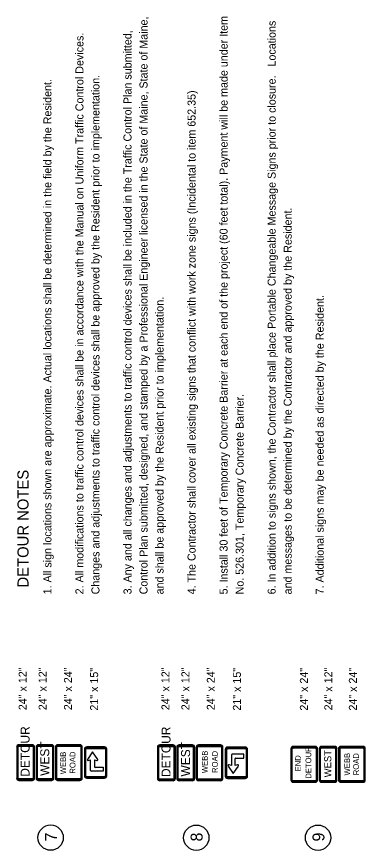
# Model space of a CAD drawing. Extents: x 1123038 to 1172987, y 554419 to 623636.
# Drawn here: x 1135053 to 1139929, y 554424 to 566087 of the extents above; entities that cross this region are included whole.
import ezdxf

# ---------------------------------------------------------------- set-up
doc = ezdxf.new("R2010")
doc.units = 0
for name, color, linetype in [('ANNOTATION', 7, 'Continuous'), ('D_Text_Standard', 7, 'Continuous'), ('Default', 7, 'Continuous')]:
    doc.layers.add(name, color=color, linetype=linetype)

msp = doc.modelspace()

# ---------------------------------------------------------------- linework, layer by layer
at = {"layer": 'D_Text_Standard'}
for centre in [(1135528, 554602), (1137565, 554601), (1139268, 554601)]:
    msp.add_circle(centre, 177, dxfattribs=at)
at = {"layer": 'Default'}
for p, q in [((1135053, 555871), (1135053, 555433)), ((1135061, 555871), (1135061, 555433)), ((1135074, 555433), (1135074, 555871)), ((1135272, 555902), (1135084, 555902)), ((1135272, 555894), (1135084, 555894)), ((1135084, 555881), (1135272, 555881)), ((1135282, 555871), (1135282, 555433)), ((1135295, 555433), (1135295, 555871)), ((1135303, 555433), (1135303, 555871)), ((1135324, 555871), (1135324, 555433)), ((1135332, 555871), (1135332, 555433)), ((1135345, 555433), (1135345, 555871)), ((1135543, 555902), (1135355, 555902)), ((1135543, 555894), (1135355, 555894)), ((1135355, 555881), (1135543, 555881)), ((1135553, 555871), (1135553, 555433)), ((1135566, 555433), (1135566, 555871)), ((1135574, 555433), (1135574, 555871)), ((1135595, 555871), (1135595, 555433)), ((1135603, 555871), (1135603, 555433)), ((1135616, 555433), (1135616, 555871)), ((1135938, 555902), (1135626, 555902)), ((1135938, 555894), (1135626, 555894)), ((1135626, 555881), (1135938, 555881)), ((1135949, 555871), (1135949, 555433)), ((1135962, 555433), (1135962, 555871)), ((1135970, 555433), (1135970, 555871)), ((1136282, 555871), (1136032, 555871)), ((1136282, 555863), (1136032, 555863)), ((1136032, 555850), (1136282, 555850)), ((1137022, 555868), (1137022, 555430)), ((1137030, 555868), (1137030, 555430)), ((1137043, 555430), (1137043, 555868)), ((1137241, 555899), (1137053, 555899)), ((1137241, 555891), (1137053, 555891)), ((1137053, 555878), (1137241, 555878)), ((1137251, 555868), (1137251, 555430)), ((1137264, 555430), (1137264, 555868)), ((1137272, 555430), (1137272, 555868)), ((1137293, 555868), (1137293, 555430)), ((1137300, 555868), (1137300, 555430)), ((1137313, 555430), (1137313, 555868)), ((1137511, 555899), (1137324, 555899)), ((1137511, 555891), (1137324, 555891)), ((1137324, 555878), (1137511, 555878)), ((1137522, 555868), (1137522, 555430)), ((1137535, 555430), (1137535, 555868)), ((1137543, 555430), (1137543, 555868)), ((1137563, 555868), (1137563, 555430)), ((1137571, 555868), (1137571, 555430)), ((1137584, 555430), (1137584, 555868)), ((1137907, 555899), (1137595, 555899)), ((1137907, 555891), (1137595, 555891)), ((1137595, 555878), (1137907, 555878)), ((1137918, 555868), (1137918, 555430)), ((1137931, 555430), (1137931, 555868)), ((1137938, 555430), (1137938, 555868)), ((1138251, 555868), (1138001, 555868)), ((1138251, 555860), (1138001, 555860)), ((1139231, 555877), (1138919, 555877)), ((1139231, 555869), (1138919, 555869)), ((1138919, 555856), (1139231, 555856)), ((1139502, 555877), (1139315, 555877)), ((1139502, 555869), (1139315, 555869)), ((1139315, 555856), (1139502, 555856)), ((1139898, 555877), (1139585, 555877)), ((1139898, 555869), (1139585, 555869)), ((1139585, 555856), (1139898, 555856)), ((1136001, 555840), (1136001, 555465)), ((1136009, 555840), (1136009, 555465)), ((1136022, 555465), (1136022, 555840)), ((1136114, 555801), (1136043, 555697)), ((1136186, 555697), (1136114, 555801)), ((1136293, 555840), (1136293, 555465)), ((1136306, 555465), (1136306, 555840)), ((1136313, 555465), (1136313, 555840)), ((1137970, 555837), (1137970, 555462)), ((1137977, 555837), (1137977, 555462)), ((1137991, 555462), (1137991, 555837)), ((1138001, 555847), (1138251, 555847)), ((1138056, 555758), (1138056, 555613)), ((1138231, 555770), (1138067, 555770)), ((1138231, 555715), (1138231, 555770)), ((1138261, 555837), (1138261, 555462)), ((1138274, 555462), (1138274, 555837)), ((1138282, 555462), (1138282, 555837)), ((1138887, 555846), (1138887, 555408)), ((1138895, 555846), (1138895, 555408)), ((1138908, 555408), (1138908, 555846)), ((1139242, 555846), (1139242, 555408)), ((1139255, 555408), (1139255, 555846)), ((1139262, 555408), (1139262, 555846)), ((1139283, 555846), (1139283, 555408)), ((1139291, 555846), (1139291, 555408)), ((1139304, 555408), (1139304, 555846)), ((1139512, 555846), (1139512, 555408)), ((1139526, 555408), (1139526, 555846)), ((1139533, 555408), (1139533, 555846)), ((1139554, 555846), (1139554, 555408)), ((1139562, 555846), (1139562, 555408)), ((1139575, 555408), (1139575, 555846)), ((1139908, 555846), (1139908, 555408)), ((1139921, 555408), (1139921, 555846)), ((1139929, 555408), (1139929, 555846)), ((1136054, 555681), (1136087, 555689)), ((1136087, 555543), (1136087, 555689)), ((1136142, 555689), (1136174, 555681)), ((1136142, 555689), (1136142, 555593)), ((1138056, 555613), (1138023, 555620)), ((1138110, 555613), (1138110, 555708)), ((1138143, 555620), (1138110, 555613)), ((1138118, 555715), (1138231, 555715)), ((1136263, 555531), (1136099, 555531)), ((1136149, 555586), (1136263, 555586)), ((1136263, 555586), (1136263, 555531)), ((1138012, 555604), (1138083, 555501)), ((1138083, 555501), (1138154, 555604)), ((1135272, 555423), (1135084, 555423)), ((1135084, 555410), (1135272, 555410)), ((1135084, 555402), (1135272, 555402)), ((1135543, 555423), (1135355, 555423)), ((1135355, 555410), (1135543, 555410)), ((1135355, 555402), (1135543, 555402)), ((1135938, 555423), (1135626, 555423)), ((1135626, 555410), (1135938, 555410)), ((1135626, 555402), (1135938, 555402)), ((1136282, 555454), (1136032, 555454)), ((1136032, 555441), (1136282, 555441)), ((1136032, 555433), (1136282, 555433)), ((1137241, 555420), (1137053, 555420)), ((1137053, 555407), (1137241, 555407)), ((1137053, 555399), (1137241, 555399)), ((1137511, 555420), (1137324, 555420)), ((1137324, 555407), (1137511, 555407)), ((1137324, 555399), (1137511, 555399)), ((1137907, 555420), (1137595, 555420)), ((1137595, 555407), (1137907, 555407)), ((1137595, 555399), (1137907, 555399)), ((1138251, 555451), (1138001, 555451)), ((1138001, 555438), (1138251, 555438)), ((1138001, 555430), (1138251, 555430)), ((1139231, 555398), (1138919, 555398)), ((1138919, 555385), (1139231, 555385)), ((1139502, 555398), (1139315, 555398)), ((1139315, 555385), (1139502, 555385)), ((1139898, 555398), (1139585, 555398)), ((1139585, 555385), (1139898, 555385)), ((1138919, 555377), (1139231, 555377)), ((1139315, 555377), (1139502, 555377)), ((1139585, 555377), (1139898, 555377))]:
    msp.add_line(p, q, dxfattribs=at)
for centre, radius, start, end in [((1135084, 555871), 31.2, 90, 180), ((1135084, 555871), 23.4, 90, 180), ((1135084, 555871), 10.4, 90, 180), ((1135272, 555871), 31.2, 0, 90), ((1135272, 555871), 23.4, 0, 90), ((1135272, 555871), 10.4, 0, 90), ((1135355, 555871), 31.2, 90, 180), ((1135355, 555871), 23.4, 90, 180), ((1135355, 555871), 10.4, 90, 180), ((1135543, 555871), 31.2, 0, 90), ((1135543, 555871), 23.4, 0, 90), ((1135543, 555871), 10.4, 0, 90), ((1135626, 555871), 31.2, 90, 180), ((1135626, 555871), 23.4, 90, 180), ((1135626, 555871), 10.4, 90, 180), ((1135938, 555871), 31.2, 0, 90), ((1135938, 555871), 23.4, 0, 90), ((1135938, 555871), 10.4, 0, 90), ((1136032, 555840), 31.2, 90, 180), ((1136032, 555840), 23.4, 90, 180), ((1136032, 555840), 10.4, 90, 180), ((1136282, 555840), 31.2, 0, 90), ((1136282, 555840), 23.4, 0, 90), ((1136282, 555840), 10.4, 0, 90), ((1137053, 555868), 31.2, 90, 180), ((1137053, 555868), 23.4, 90, 180), ((1137053, 555868), 10.4, 90, 180), ((1137241, 555868), 31.2, 0, 90), ((1137241, 555868), 23.4, 0, 90), ((1137241, 555868), 10.4, 0, 90), ((1137324, 555868), 31.2, 90, 180), ((1137324, 555868), 23.4, 90, 180), ((1137324, 555868), 10.4, 90, 180), ((1137511, 555868), 31.2, 0, 90), ((1137511, 555868), 23.4, 0, 90), ((1137511, 555868), 10.4, 0, 90), ((1137595, 555868), 31.2, 90, 180), ((1137595, 555868), 23.4, 90, 180), ((1137595, 555868), 10.4, 90, 180), ((1137907, 555868), 31.2, 0, 90), ((1137907, 555868), 23.4, 0, 90), ((1137907, 555868), 10.4, 0, 90), ((1138001, 555837), 31.2, 90, 180), ((1138001, 555837), 23.4, 90, 180), ((1138251, 555837), 31.2, 0, 90), ((1138251, 555837), 23.4, 0, 90), ((1138919, 555846), 31.2, 90, 180), ((1138919, 555846), 23.4, 90, 180), ((1138919, 555846), 10.4, 90, 180), ((1139231, 555846), 31.2, 0, 90), ((1139231, 555846), 23.4, 0, 90), ((1139231, 555846), 10.4, 0, 90), ((1139315, 555846), 31.2, 90, 180), ((1139315, 555846), 23.4, 90, 180), ((1139315, 555846), 10.4, 90, 180), ((1139502, 555846), 31.2, 0, 90), ((1139502, 555846), 23.4, 0, 90), ((1139502, 555846), 10.4, 0, 90), ((1139585, 555846), 31.2, 90, 180), ((1139585, 555846), 23.4, 90, 180), ((1139585, 555846), 10.4, 90, 180), ((1139898, 555846), 31.2, 0, 90), ((1139898, 555846), 23.4, 0, 90), ((1139898, 555846), 10.4, 0, 90), ((1138001, 555837), 10.4, 90, 180), ((1138067, 555758), 11.7, 90, 180), ((1138251, 555837), 10.4, 0, 90), ((1136052, 555691), 10.4, 147.7244, 282.9503), ((1136177, 555691), 10.4, 257.0497, 32.2757), ((1138020, 555610), 10.4, 77.0497, 212.2757), ((1138118, 555708), 7.81, 90, 180), ((1138145, 555610), 10.4, 327.7244, 102.9504), ((1136099, 555543), 11.7, 180, 270), ((1136149, 555593), 7.81, 180, 270), ((1135084, 555433), 31.2, 180, 270), ((1135084, 555433), 23.4, 180, 270), ((1135084, 555433), 10.4, 180, 270), ((1135272, 555433), 31.2, 270, 0), ((1135272, 555433), 23.4, 270, 0), ((1135272, 555433), 10.4, 270, 0), ((1135355, 555433), 31.2, 180, 270), ((1135355, 555433), 23.4, 180, 270), ((1135355, 555433), 10.4, 180, 270), ((1135543, 555433), 31.2, 270, 0), ((1135543, 555433), 23.4, 270, 0), ((1135543, 555433), 10.4, 270, 0), ((1135626, 555433), 31.2, 180, 270), ((1135626, 555433), 23.4, 180, 270), ((1135626, 555433), 10.4, 180, 270), ((1135938, 555433), 31.2, 270, 0), ((1135938, 555433), 23.4, 270, 0), ((1135938, 555433), 10.4, 270, 0), ((1136032, 555465), 31.2, 180, 270), ((1136032, 555465), 23.4, 180, 270), ((1136032, 555465), 10.4, 180, 270), ((1136282, 555465), 31.2, 270, 0), ((1136282, 555465), 23.4, 270, 0), ((1136282, 555465), 10.4, 270, 0), ((1137053, 555430), 31.2, 180, 270), ((1137053, 555430), 23.4, 180, 270), ((1137053, 555430), 10.4, 180, 270), ((1137241, 555430), 31.2, 270, 0), ((1137241, 555430), 23.4, 270, 0), ((1137241, 555430), 10.4, 270, 0), ((1137324, 555430), 31.2, 180, 270), ((1137324, 555430), 23.4, 180, 270), ((1137324, 555430), 10.4, 180, 270), ((1137511, 555430), 31.2, 270, 0), ((1137511, 555430), 23.4, 270, 0), ((1137511, 555430), 10.4, 270, 0), ((1137595, 555430), 31.2, 180, 270), ((1137595, 555430), 23.4, 180, 270), ((1137595, 555430), 10.4, 180, 270), ((1137907, 555430), 31.2, 270, 0), ((1137907, 555430), 23.4, 270, 0), ((1137907, 555430), 10.4, 270, 0), ((1138001, 555462), 31.2, 180, 270), ((1138001, 555462), 23.4, 180, 270), ((1138001, 555462), 10.4, 180, 270), ((1138251, 555462), 31.2, 270, 0), ((1138251, 555462), 23.4, 270, 0), ((1138251, 555462), 10.4, 270, 0), ((1138919, 555408), 31.2, 180, 270), ((1138919, 555408), 23.4, 180, 270), ((1138919, 555408), 10.4, 180, 270), ((1139231, 555408), 31.2, 270, 0), ((1139231, 555408), 23.4, 270, 0), ((1139231, 555408), 10.4, 270, 0), ((1139315, 555408), 31.2, 180, 270), ((1139315, 555408), 23.4, 180, 270), ((1139315, 555408), 10.4, 180, 270), ((1139502, 555408), 31.2, 270, 0), ((1139502, 555408), 23.4, 270, 0), ((1139502, 555408), 10.4, 270, 0), ((1139585, 555408), 31.2, 180, 270), ((1139585, 555408), 23.4, 180, 270), ((1139585, 555408), 10.4, 180, 270), ((1139898, 555408), 31.2, 270, 0), ((1139898, 555408), 23.4, 270, 0), ((1139898, 555408), 10.4, 270, 0)]:
    msp.add_arc(centre, radius, start, end, dxfattribs=at)

# ---------------------------------------------------------------- texts
at = {"layer": 'ANNOTATION'}
msp.add_text('DETOUR NOTES', height=155, rotation=90, dxfattribs=at).set_placement((1135219, 558101))
at = {"layer": 'D_Text_Standard'}
for s, height, p in [('24" x 12"', 112, (1135193, 556385)), ('24" x 12"', 112, (1135472, 556385)), ('24" x 24"', 112, (1135827, 556385)), ('21" x 15"', 112, (1136192, 556379)), ('24" x 12"', 112, (1137190, 556385)), ('24" x 12"', 112, (1137469, 556385)), ('24" x 24"', 112, (1137824, 556385)), ('21" x 15"', 112, (1138189, 556379)), ('24" x 24"', 112, (1139126, 556379)), ('24" x 12"', 112, (1139468, 556382)), ('24" x 24"', 112, (1139811, 556380)), ('7', 167, (1135615, 554550)), ('8', 167, (1137653, 554548)), ('9', 167, (1139357, 554548))]:
    msp.add_text(s, height=height, rotation=90, dxfattribs=at).set_placement(p)
at = {"layer": 'Default'}
for s, height, p in [('Control Plan submitted, designed, and stamped by a Professional Engineer licensed in the State of Maine, State of Maine, ', 112, (1136883, 558005)), ('5. Install 30 feet of Temporary Concrete Barrier at each end of the project (60 feet total). Payment will be made under Item ', 112, (1138003, 558005)), ('6. In addition to signs shown, the Contractor shall place Portable Changeable Message Signs prior to closure.   Locations ', 112, (1138675, 558005)), ('3. Any and all changes and adjustments to traffic control devices shall be included in the Traffic Control Plan submitted, ', 112, (1136659, 558005)), ('2. All modifications to traffic control devices shall be in accordance with the Manual on Uniform Traffic Control Devices. ', 112, (1135987, 558005)), ('1. All sign locations shown are approximate. Actual locations shall be determined in the field by the Resident.', 112, (1135539, 558005)), ('Changes and adjustments to traffic control devices shall be approved by the Resident prior to implementation.', 112, (1136211, 558005)), ('4. The Contractor shall cover all existing signs that conflict with work zone signs (Incidental to item 652.35)', 112, (1137555, 558005)), ('and messages to be determined by the Contractor and approved by the Resident.', 112, (1138899, 558005)), ('and shall be approved by the Resident prior to implementation.', 112, (1137107, 558005)), ('7. Additional signs may be needed as directed by the Resident.', 112, (1139347, 558005)), ('No. 526.301, Temporary Concrete Barrier.', 112, (1138227, 558005)), ('DETOUR', 125, (1135233, 555454)), ('DETOUR', 125, (1137204, 555450)), ('WEST', 125, (1135508, 555466)), ('WEST', 125, (1137478, 555457)), ('DETOUR', 80, (1139173, 555427)), ('WEBB', 80, (1135742, 555489)), ('ROAD', 80, (1135875, 555497)), ('WEBB', 80, (1137725, 555504)), ('ROAD', 80, (1137865, 555507)), ('END', 80, (1139027, 555528)), ('WEST', 99.3, (1139453, 555445)), ('WEBB', 80, (1139715, 555472)), ('ROAD', 80, (1139839, 555475))]:
    msp.add_text(s, height=height, rotation=90, dxfattribs=at).set_placement(p)

doc.saveas('drawing.dxf')
